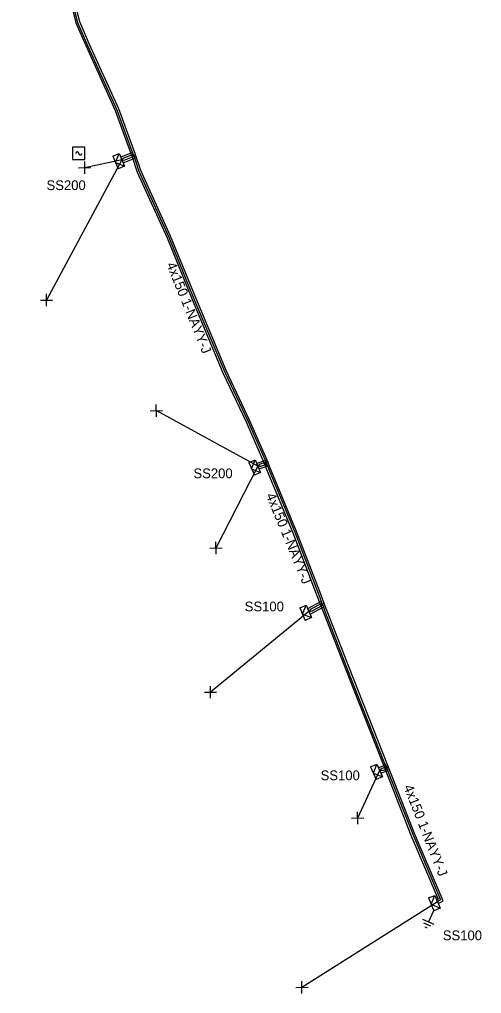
# Model space of a CAD drawing. Extents: x -762504 to -761250, y -1152974 to -1152253.
# Drawn here: x -761495.3 to -761448.3, y -1152763.1 to -1152663.9 of the extents above; entities that cross this region are included whole.
import ezdxf

# ---------------------------------------------------------------- set-up
doc = ezdxf.new("R2010")
doc.units = 0
for name, color, linetype in [('Vrstva 15', 7, 'Continuous'), ('Vrstva 20', 7, 'Continuous'), ('Vrstva 31', 7, 'Continuous'), ('Vrstva 33', 7, 'Continuous'), ('Vrstva 34', 7, 'Continuous'), ('Vrstva 5', 7, 'Continuous'), ('Vrstva 59', 7, 'Continuous'), ('Vrstva 6', 7, 'Continuous')]:
    doc.layers.add(name, color=color, linetype=linetype)

msp = doc.modelspace()

# ---------------------------------------------------------------- linework, layer by layer
at = {"layer": 'Vrstva 15'}
for points in [[(-761453.094, -1152756.093), (-761454.235, -1152755.585)], [(-761453.156, -1152754.697), (-761453.664, -1152755.839)], [(-761453.44, -1152756.278), (-761454.159, -1152755.958)], [(-761453.919, -1152756.41), (-761454.036, -1152756.358)], [(-761453.797, -1152756.464), (-761453.919, -1152756.41)]]:
    msp.add_lwpolyline(points, dxfattribs=at)
at = {"layer": 'Vrstva 20'}
for points in [[(-761483.88, -1152677.82), (-761483.5, -1152677.68), (-761485.19, -1152673.02), (-761488.17, -1152666.46), (-761489.18, -1152664.15), (-761489.95, -1152661.09), (-761493.24, -1152652.1), (-761494.34, -1152650.72), (-761494.93, -1152649.06), (-761495.31, -1152649.2), (-761494.7, -1152650.92), (-761493.6, -1152652.3), (-761490.33, -1152661.21), (-761489.56, -1152664.27), (-761488.53, -1152666.62), (-761485.57, -1152673.18)], [(-761484.99, -1152677.94), (-761484.77, -1152678.5), (-761483.58, -1152678.03), (-761483.8, -1152677.47)], [(-761470.35, -1152709.2), (-761469.99, -1152709.04), (-761471.88, -1152704.72), (-761474.24, -1152699.75), (-761477.37, -1152692.28), (-761479.92, -1152686), (-761482.96, -1152679.31), (-761483.5, -1152677.69), (-761483.88, -1152677.81), (-761483.34, -1152679.45), (-761480.28, -1152686.16), (-761477.74, -1152692.44), (-761474.6, -1152699.91), (-761472.24, -1152704.88)], [(-761471.13, -1152709.13), (-761470.95, -1152709.69), (-761470.08, -1152709.4), (-761470.26, -1152708.84)], [(-761464.66, -1152723.55), (-761464.28, -1152723.41), (-761464.71, -1152722.29), (-761467.1, -1152716.06), (-761469.81, -1152709.5), (-761469.98, -1152709.05), (-761470.36, -1152709.19), (-761470.19, -1152709.64), (-761467.48, -1152716.2), (-761465.09, -1152722.43)], [(-761464.61, -1152723.21), (-761466, -1152723.93), (-761465.72, -1152724.47), (-761464.33, -1152723.75)], [(-761458.11, -1152740.21), (-761457.73, -1152740.07), (-761461.38, -1152730.87), (-761464.28, -1152723.41), (-761464.66, -1152723.55), (-761461.76, -1152731.01)], [(-761458.75, -1152740.13), (-761458.53, -1152740.69), (-761457.81, -1152740.42), (-761458.03, -1152739.86)], [(-761452.85, -1152753.61), (-761452.65, -1152753.95), (-761452.18, -1152753.67), (-761455.08, -1152746.83), (-761457.73, -1152740.07), (-761458.11, -1152740.21), (-761455.46, -1152746.99), (-761452.68, -1152753.51)]]:
    msp.add_lwpolyline(points, close=True, dxfattribs=at)
at = {"layer": 'Vrstva 31'}
for points in [[(-761485.8, -1152677.846), (-761485.155, -1152677.573), (-761484.608, -1152678.861), (-761485.253, -1152679.135)], [(-761485.8, -1152677.846), (-761485.253, -1152679.135)], [(-761485.526, -1152678.491), (-761485.155, -1152677.573)], [(-761485.526, -1152678.491), (-761484.608, -1152678.861)], [(-761471.966, -1152709.052), (-761471.327, -1152708.768), (-761470.757, -1152710.047), (-761471.397, -1152710.331)], [(-761471.966, -1152709.052), (-761471.397, -1152710.331)], [(-761471.681, -1152709.692), (-761471.327, -1152708.768)], [(-761471.681, -1152709.692), (-761470.757, -1152710.047)], [(-761466.78, -1152723.826), (-761466.135, -1152723.553), (-761465.588, -1152724.841), (-761466.233, -1152725.115)], [(-761466.78, -1152723.826), (-761466.233, -1152725.115)], [(-761466.506, -1152724.471), (-761466.135, -1152723.553)], [(-761466.506, -1152724.471), (-761465.588, -1152724.841)], [(-761459.566, -1152740.052), (-761458.927, -1152739.768), (-761458.357, -1152741.047), (-761458.997, -1152741.331)], [(-761459.281, -1152740.692), (-761458.927, -1152739.768)], [(-761459.566, -1152740.052), (-761458.997, -1152741.331)], [(-761459.281, -1152740.692), (-761458.357, -1152741.047)], [(-761453.663, -1152753.39), (-761453.014, -1152753.128), (-761452.49, -1152754.426), (-761453.139, -1152754.688)], [(-761453.663, -1152753.39), (-761453.139, -1152754.688)], [(-761453.401, -1152754.039), (-761453.014, -1152753.128)], [(-761453.401, -1152754.039), (-761452.49, -1152754.426)]]:
    msp.add_lwpolyline(points, dxfattribs=at)
at = {"layer": 'Vrstva 34'}
for points in [[(-761488.646, -1152676.936), (-761489.896, -1152676.936)], [(-761489.896, -1152676.936), (-761489.896, -1152678.186)], [(-761488.646, -1152678.186), (-761488.646, -1152676.936)], [(-761489.896, -1152678.186), (-761488.646, -1152678.186)], [(-761489.271, -1152677.561), (-761489.272, -1152677.545), (-761489.274, -1152677.53), (-761489.278, -1152677.514), (-761489.284, -1152677.499), (-761489.291, -1152677.485), (-761489.3, -1152677.472), (-761489.31, -1152677.459), (-761489.321, -1152677.448), (-761489.333, -1152677.438), (-761489.347, -1152677.429), (-761489.361, -1152677.422), (-761489.376, -1152677.416), (-761489.391, -1152677.412), (-761489.407, -1152677.409), (-761489.423, -1152677.408), (-761489.439, -1152677.409), (-761489.455, -1152677.411), (-761489.47, -1152677.415), (-761489.485, -1152677.421), (-761489.499, -1152677.428), (-761489.513, -1152677.437), (-761489.525, -1152677.447), (-761489.537, -1152677.458), (-761489.547, -1152677.47), (-761489.555, -1152677.484), (-761489.563, -1152677.498), (-761489.569, -1152677.513), (-761489.573, -1152677.528), (-761489.575, -1152677.544), (-761489.576, -1152677.56), (-761489.576, -1152677.561)], [(-761489.271, -1152677.561), (-761489.271, -1152677.577), (-761489.268, -1152677.593), (-761489.265, -1152677.608), (-761489.259, -1152677.623), (-761489.252, -1152677.637), (-761489.244, -1152677.65), (-761489.235, -1152677.663), (-761489.224, -1152677.674), (-761489.212, -1152677.684), (-761489.199, -1152677.693), (-761489.185, -1152677.7), (-761489.17, -1152677.706), (-761489.155, -1152677.711), (-761489.14, -1152677.713), (-761489.124, -1152677.714), (-761489.108, -1152677.714), (-761489.093, -1152677.712), (-761489.077, -1152677.708), (-761489.063, -1152677.703), (-761489.049, -1152677.696), (-761489.035, -1152677.687), (-761489.023, -1152677.678), (-761489.012, -1152677.667), (-761489.001, -1152677.655), (-761488.993, -1152677.642), (-761488.985, -1152677.628), (-761488.979, -1152677.613), (-761488.975, -1152677.598), (-761488.972, -1152677.583), (-761488.971, -1152677.567), (-761488.971, -1152677.566)], [(-761489.285, -1152679.021), (-761488.035, -1152678.999)], [(-761488.649, -1152679.635), (-761488.671, -1152678.385)], [(-761492.549, -1152693.125), (-761492.571, -1152691.875)], [(-761493.185, -1152692.511), (-761491.935, -1152692.489)], [(-761482.005, -1152703.761), (-761480.755, -1152703.739)], [(-761481.369, -1152704.375), (-761481.391, -1152703.125)], [(-761475.935, -1152717.761), (-761474.685, -1152717.739)], [(-761475.299, -1152718.375), (-761475.321, -1152717.125)], [(-761475.85, -1152733.055), (-761475.871, -1152731.805)], [(-761476.485, -1152732.441), (-761475.236, -1152732.419)], [(-761460.869, -1152745.875), (-761460.891, -1152744.625)], [(-761461.505, -1152745.261), (-761460.255, -1152745.239)], [(-761467.185, -1152762.511), (-761465.935, -1152762.489)], [(-761466.549, -1152763.125), (-761466.571, -1152761.875)]]:
    msp.add_lwpolyline(points, dxfattribs=at)
at = {"layer": 'Vrstva 5'}
msp.add_lwpolyline([(-761490.17, -1152661.16), (-761489.4, -1152664.22), (-761488.38, -1152666.55), (-761485.41, -1152673.11), (-761484.01, -1152676.95), (-761483.73, -1152677.66), (-761484.71, -1152678.05), (-761484.88, -1152678.22), (-761484.65, -1152678.24), (-761483.65, -1152677.84), (-761483.54, -1152678.21), (-761483.15, -1152679.38), (-761480.1, -1152686.08), (-761477.56, -1152692.36), (-761474.42, -1152699.83), (-761472.06, -1152704.8), (-761470.44, -1152708.5), (-761470.2, -1152709.02), (-761470.8, -1152709.22), (-761471.04, -1152709.41), (-761470.75, -1152709.42), (-761470.14, -1152709.21), (-761469.9, -1152709.81), (-761467.29, -1152716.13), (-761464.9, -1152722.36), (-761464.7, -1152722.88), (-761464.52, -1152723.39), (-761465.65, -1152723.98), (-761465.86, -1152724.2), (-761465.51, -1152724.13), (-761464.42, -1152723.57), (-761464.2, -1152724.27), (-761461.6, -1152730.95), (-761458.13, -1152739.69), (-761457.95, -1152740.05), (-761458.39, -1152740.21), (-761458.64, -1152740.41), (-761458.26, -1152740.37), (-761457.88, -1152740.23), (-761457.69, -1152740.74), (-761455.27, -1152746.91), (-761452.43, -1152753.59), (-761452.75, -1152753.78)], dxfattribs=at)
at = {"layer": 'Vrstva 59'}
for points in [[(-761484.88, -1152678.22), (-761492.56, -1152692.5)], [(-761484.88, -1152678.22), (-761488.66, -1152679.01)], [(-761471.04, -1152709.41), (-761481.38, -1152703.75)], [(-761471.04, -1152709.41), (-761475.31, -1152717.75)], [(-761465.86, -1152724.2), (-761475.86, -1152732.43)], [(-761458.64, -1152740.41), (-761460.88, -1152745.25)], [(-761452.75, -1152753.78), (-761466.56, -1152762.5)]]:
    msp.add_lwpolyline(points, dxfattribs=at)

# ---------------------------------------------------------------- texts
at = {"layer": 'Vrstva 33'}
for s, p in [('SS200', (-761492.56, -1152681.29)), ('SS200', (-761477.6, -1152710.64)), ('SS100', (-761472.38, -1152724.2)), ('SS100', (-761464.65, -1152741.4)), ('SS100', (-761452.21, -1152757.7))]:
    msp.add_text(s, height=0.9943, dxfattribs=at).set_placement(p)
at = {"layer": 'Vrstva 6'}
for height, rotation, p in [(0.99428, 292.02129, (-761480.37, -1152688.87)), (0.99429, 292.446, (-761470.24, -1152712.38)), (0.99429, 291.377, (-761456.22, -1152742.07))]:
    msp.add_text('4x150 1-NAYY-J', height=height, rotation=rotation, dxfattribs=at).set_placement(p)

doc.saveas('drawing.dxf')
